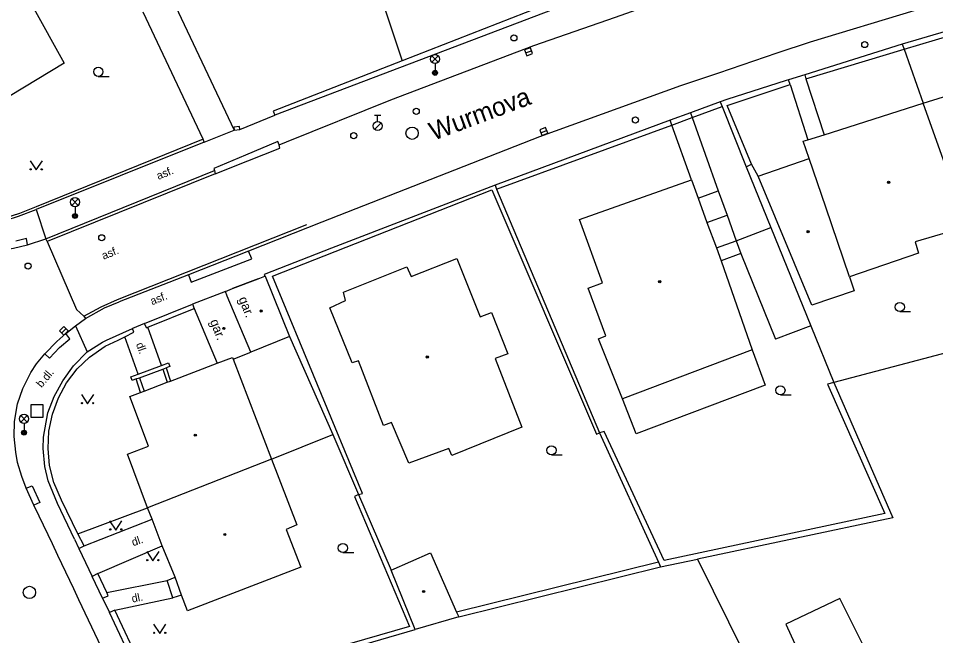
# Model space of a CAD drawing. Extents: x -600391 to -599491, y -1160176 to -1159402.
# Drawn here: x -600225 to -600150.5, y -1159694.5 to -1159644.4 of the extents above; entities that cross this region are included whole.
import ezdxf

# ---------------------------------------------------------------- set-up
doc = ezdxf.new("R2010")
doc.units = 0
for name, color, linetype in [('Level 10', 7, 'Continuous'), ('Level 11', 7, 'Continuous'), ('Level 26', 7, 'Continuous'), ('Level 27', 7, 'Continuous'), ('Level 28', 7, 'Continuous'), ('Level 33', 7, 'Continuous'), ('Level 36', 7, 'Continuous'), ('Level 39', 7, 'Continuous'), ('Level 40', 7, 'Continuous'), ('Level 41', 7, 'Continuous'), ('Level 5', 7, 'Continuous'), ('Level 50', 7, 'Continuous'), ('Level 51', 7, 'Continuous'), ('Level 6', 7, 'Continuous'), ('Level 7', 7, 'Continuous'), ('Level 8', 7, 'Continuous')]:
    doc.layers.add(name, color=color, linetype=linetype)

msp = doc.modelspace()

# ---------------------------------------------------------------- linework, layer by layer
at = {"layer": 'Level 10'}
for points in [[(-600203.81, -1159654.71), (-600203.2, -1159654.46), (-600194.73, -1159651.05), (-600183.13, -1159646.66), (-600176.51, -1159644.35), (-600173.89, -1159643.43), (-600161.79, -1159639.45), (-600139.81, -1159632.73), (-600117.42, -1159627.38), (-600101.85, -1159624.11), (-600096.85, -1159623.48), (-600094.37, -1159623.17), (-600090.07, -1159622.63), (-600079.63, -1159622.19), (-600061.86, -1159622.84)], [(-600091.45, -1159629.86), (-600119.7, -1159635.07), (-600134.36, -1159638.83), (-600136.31, -1159639.33), (-600143.85, -1159641.26), (-600160.7, -1159646.37), (-600163.4, -1159647.28), (-600168.14, -1159648.88), (-600171.23, -1159649.93), (-600182.66, -1159654.06), (-600190.19, -1159657.01), (-600200.329, -1159660.99), (-600206.29, -1159663.33)], [(-600208.99, -1159657.06), (-600206.35, -1159656.02), (-600203.75, -1159654.97), (-600203.81, -1159654.71)], [(-600222.75, -1159662.34), (-600209.07, -1159656.8)], [(-600209.07, -1159656.8), (-600208.99, -1159657.06)], [(-600224.23, -1159662.82), (-600222.75, -1159662.34)], [(-600226.58, -1159663.28), (-600225.37, -1159663.1), (-600224.23, -1159662.82)], [(-600206.29, -1159663.33), (-600211.18, -1159665.25)], [(-600211.18, -1159665.25), (-600216.81, -1159667.45)], [(-600219.54, -1159668.81), (-600218, -1159667.95), (-600216.81, -1159667.45)], [(-600220.33, -1159669.41), (-600219.54, -1159668.81)], [(-600221.14, -1159670.03), (-600220.33, -1159669.41)], [(-600222.84, -1159671.66), (-600221.85, -1159670.68), (-600221.14, -1159670.03)], [(-600224.35, -1159682.57), (-600224.7, -1159681.62), (-600225.05, -1159680.48), (-600225.18, -1159679.65), (-600225.32, -1159678.37), (-600225.29, -1159677.17), (-600225.05, -1159675.73), (-600224.62, -1159674.49), (-600223.97, -1159673.19), (-600223.52, -1159672.49), (-600222.84, -1159671.66)], [(-600223.72, -1159683.94), (-600224.35, -1159682.57)], [(-600197.66, -1159738.93), (-600199.99, -1159733.97), (-600200.43, -1159733.05), (-600201.7, -1159730.35), (-600202.12, -1159729.41), (-600205.92, -1159721.47), (-600206.37, -1159720.55), (-600209.98, -1159712.86), (-600210.42, -1159711.95), (-600217.28, -1159697.51), (-600217.72, -1159696.59), (-600220.08, -1159691.63), (-600220.49, -1159690.73), (-600221.79, -1159688.03), (-600222.22, -1159687.1), (-600223.28, -1159684.84), (-600223.72, -1159683.94)]]:
    msp.add_lwpolyline(points, dxfattribs=at)
at = {"layer": 'Level 11'}
for points in [[(-600209.99, -1159654.25), (-600214.85, -1159643.95)], [(-600161.04, -1159649.35), (-600159.57, -1159653.89)], [(-600162.32, -1159649.81), (-600160.88, -1159654.3)], [(-600171.93, -1159653.1), (-600170.28, -1159652.49)], [(-600170.28, -1159652.49), (-600168.15, -1159658.45)], [(-600170.34, -1159657.54), (-600171.93, -1159653.1)], [(-600203.81, -1159654.71), (-600203.92, -1159654.45), (-600206.53, -1159655.55), (-600209.1, -1159656.63), (-600209.07, -1159656.8)], [(-600164.91, -1159657.24), (-600165.45, -1159656.27)], [(-600208.99, -1159657.06), (-600222.63, -1159662.55)], [(-600169.79, -1159659.04), (-600168.15, -1159658.45)], [(-600168.15, -1159658.45), (-600167.44, -1159660.43)], [(-600223.53, -1159659.97), (-600222.75, -1159662.34)], [(-600169.07, -1159661.01), (-600167.44, -1159660.43)], [(-600167.44, -1159660.43), (-600166.7, -1159662.5)], [(-600219.66, -1159668.6), (-600218.25, -1159667.85), (-600216.93, -1159667.27), (-600201.55, -1159661.18)], [(-600166.7, -1159662.5), (-600163.89, -1159661.43)], [(-600224.23, -1159662.82), (-600224.33, -1159662.3), (-600225.2, -1159662.53)], [(-600222.63, -1159662.55), (-600222.65, -1159662.56), (-600222.75, -1159662.34)], [(-600222.63, -1159662.55), (-600220.27, -1159668.06), (-600219.66, -1159668.6)], [(-600168.31, -1159663.08), (-600166.7, -1159662.5)], [(-600166.7, -1159662.5), (-600166.33, -1159663.53)], [(-600211.18, -1159665.25), (-600210.94, -1159665.86), (-600206.02, -1159663.97), (-600206.29, -1159663.33)], [(-600166.33, -1159663.53), (-600167.93, -1159664.11)], [(-600166.33, -1159663.53), (-600163.5, -1159670.47)], [(-600219.66, -1159668.6), (-600219.54, -1159668.81)], [(-600220.33, -1159669.41), (-600219.39, -1159671.52)], [(-600213.36, -1159672.62), (-600214.48, -1159669.5)], [(-600160.65, -1159669.39), (-600163.5, -1159670.47)], [(-600222.84, -1159671.66), (-600222.45, -1159672.02), (-600221.64, -1159671.16), (-600220.8, -1159670.44), (-600221.14, -1159670.03)], [(-600215.26, -1159673.32), (-600216.34, -1159670.29)], [(-600165.41, -1159671.35), (-600164.35, -1159674.2), (-600174.81, -1159678.17), (-600175.94, -1159675.32)], [(-600215.43, -1159673.71), (-600215.74, -1159673.83), (-600215.85, -1159673.54), (-600215.26, -1159673.32), (-600213.36, -1159672.62), (-600212.78, -1159672.4), (-600212.68, -1159672.69), (-600212.98, -1159672.8)], [(-600215.15, -1159673.61), (-600213.26, -1159672.91)], [(-600213.26, -1159672.91), (-600212.98, -1159672.8)], [(-600213.26, -1159672.91), (-600212.89, -1159673.98)], [(-600212.98, -1159672.8), (-600212.62, -1159673.88)], [(-600215.43, -1159673.71), (-600215.15, -1159673.61)], [(-600215.07, -1159674.81), (-600215.43, -1159673.71)], [(-600215.15, -1159673.61), (-600214.76, -1159674.69)], [(-600224.35, -1159682.57), (-600223.86, -1159682.38), (-600223.23, -1159683.73), (-600223.72, -1159683.94)], [(-600220.14, -1159686.27), (-600214.49, -1159684.17)], [(-600219.65, -1159687.26), (-600214.13, -1159685.09)], [(-600218.53, -1159689.51), (-600213.3, -1159687.24)], [(-600217.81, -1159691.03), (-600212.91, -1159690.07)], [(-600217.14, -1159692.47), (-600212.43, -1159691.46)], [(-600162.66, -1159693.62), (-600160.75, -1159697.8), (-600156.28, -1159695.54), (-600158.28, -1159691.52), (-600162.66, -1159693.62)]]:
    msp.add_lwpolyline(points, dxfattribs=at)
at = {"layer": 'Level 26'}
msp.add_lwpolyline([(-600223.97, -1159676.82), (-600222.97, -1159676.82), (-600222.97, -1159675.82), (-600223.97, -1159675.82)], close=True, dxfattribs=at)
at = {"layer": 'Level 27'}
for p, q in [((-600183.795, -1159647.246), (-600183.325, -1159647.074)), ((-600182.563, -1159653.722), (-600182.097, -1159653.538)), ((-600221.457, -1159669.977), (-600221.103, -1159669.623))]:
    msp.add_line(p, q, dxfattribs=at)
for points in [[(-600183.708, -1159647.481), (-600183.239, -1159647.308), (-600183.412, -1159646.839), (-600183.881, -1159647.011)], [(-600182.471, -1159653.954), (-600182.006, -1159653.771), (-600182.189, -1159653.306), (-600182.654, -1159653.489)], [(-600221.28, -1159670.154), (-600220.926, -1159669.8), (-600221.28, -1159669.446), (-600221.634, -1159669.8)]]:
    msp.add_lwpolyline(points, close=True, dxfattribs=at)
for centre in [(-600193.01, -1159653.77), (-600224.08, -1159691.03)]:
    msp.add_circle(centre, 0.5, dxfattribs=at)
at = {"layer": 'Level 28'}
for p, q in [((-600196.06, -1159652.305), (-600195.56, -1159652.305)), ((-600195.81, -1159652.805), (-600195.81, -1159652.305)), ((-600196.068, -1159653.452), (-600195.538, -1159652.922))]:
    msp.add_line(p, q, dxfattribs=at)
for centre, radius in [((-600184.75, -1159646.03), 0.25), ((-600156.26, -1159646.57), 0.25), ((-600192.68, -1159651.99), 0.25), ((-600174.88, -1159652.69), 0.25), ((-600195.81, -1159653.18), 0.375), ((-600197.75, -1159653.96), 0.25), ((-600218.21, -1159662.25), 0.25), ((-600224.19, -1159664.55), 0.25)]:
    msp.add_circle(centre, radius, dxfattribs=at)
at = {"layer": 'Level 33'}
for p, q in [((-600191.415, -1159648.01), (-600190.885, -1159647.48)), ((-600191.415, -1159647.48), (-600190.885, -1159648.01)), ((-600191.15, -1159648.12), (-600191.15, -1159648.87)), ((-600220.645, -1159659.62), (-600220.115, -1159659.09)), ((-600220.645, -1159659.09), (-600220.115, -1159659.62)), ((-600220.38, -1159659.73), (-600220.38, -1159660.48)), ((-600224.785, -1159677.21), (-600224.255, -1159676.68)), ((-600224.785, -1159676.68), (-600224.255, -1159677.21)), ((-600224.52, -1159677.32), (-600224.52, -1159678.07))]:
    msp.add_line(p, q, dxfattribs=at)
for centre, radius in [((-600191.15, -1159647.745), 0.375), ((-600191.15, -1159648.87), 0.2), ((-600191.15, -1159648.87), 0.145), ((-600191.15, -1159648.87), 0.0876), ((-600220.38, -1159659.355), 0.375), ((-600220.38, -1159660.48), 0.2), ((-600220.38, -1159660.48), 0.145), ((-600220.38, -1159660.48), 0.0876), ((-600224.52, -1159676.945), 0.375), ((-600224.52, -1159678.07), 0.2), ((-600224.52, -1159678.07), 0.145), ((-600224.52, -1159678.07), 0.0876)]:
    msp.add_circle(centre, radius, dxfattribs=at)
at = {"layer": 'Level 36'}
for p, q in [((-600218.49, -1159649.155), (-600217.615, -1159649.155)), ((-600153.42, -1159668.245), (-600152.545, -1159668.245)), ((-600163.11, -1159675.005), (-600162.235, -1159675.005)), ((-600181.7, -1159679.875), (-600180.825, -1159679.875)), ((-600198.63, -1159687.805), (-600197.755, -1159687.805))]:
    msp.add_line(p, q, dxfattribs=at)
for points in [[(-600224.03, -1159656), (-600223.53, -1159656.75), (-600223.03, -1159656)], [(-600219.86, -1159674.97), (-600219.36, -1159675.72), (-600218.86, -1159674.97)], [(-600217.57, -1159685.22), (-600217.07, -1159685.97), (-600216.57, -1159685.22)], [(-600214.56, -1159687.71), (-600214.06, -1159688.46), (-600213.56, -1159687.71)], [(-600214, -1159693.61), (-600213.5, -1159694.36), (-600213, -1159693.61)]]:
    msp.add_lwpolyline(points, dxfattribs=at)
for centre, radius in [((-600218.49, -1159648.78), 0.375), ((-600223.98, -1159656.7), 0.05), ((-600223.081, -1159656.7), 0.05), ((-600153.42, -1159667.87), 0.375), ((-600163.11, -1159674.63), 0.375), ((-600219.81, -1159675.67), 0.05), ((-600218.911, -1159675.67), 0.05), ((-600181.7, -1159679.5), 0.375), ((-600217.52, -1159685.92), 0.05), ((-600216.621, -1159685.92), 0.05), ((-600198.63, -1159687.43), 0.375), ((-600214.51, -1159688.41), 0.05), ((-600213.611, -1159688.41), 0.05), ((-600213.95, -1159694.31), 0.05), ((-600213.051, -1159694.31), 0.05)]:
    msp.add_circle(centre, radius, dxfattribs=at)
at = {"layer": 'Level 39'}
for centre, radius in [((-600154.32, -1159657.75), 0.09), ((-600154.32, -1159657.75), 0.0398), ((-600160.86, -1159661.76), 0.09), ((-600160.86, -1159661.76), 0.0398), ((-600172.91, -1159665.82), 0.09), ((-600172.91, -1159665.82), 0.0398), ((-600205.27, -1159668.19), 0.09), ((-600205.27, -1159668.19), 0.0398), ((-600208.3, -1159669.61), 0.09), ((-600208.3, -1159669.61), 0.0398), ((-600191.78, -1159671.93), 0.09), ((-600191.78, -1159671.93), 0.0398), ((-600210.62, -1159678.27), 0.09), ((-600210.62, -1159678.27), 0.0398), ((-600208.22, -1159686.33), 0.09), ((-600208.22, -1159686.33), 0.0398), ((-600192.08, -1159690.96), 0.09), ((-600192.08, -1159690.96), 0.0398)]:
    msp.add_circle(centre, radius, dxfattribs=at)
at = {"layer": 'Level 5'}
for points in [[(-600223.86, -1159643.39), (-600221.27, -1159648.07)], [(-600221.27, -1159648.07), (-600225.65, -1159650.73)], [(-600151.51, -1159651.33), (-600146.13, -1159649.64)], [(-600159.57, -1159653.89), (-600151.51, -1159651.33)], [(-600149.59, -1159656.7), (-600151.51, -1159651.33)], [(-600160.88, -1159654.3), (-600159.57, -1159653.89)], [(-600161.25, -1159654.42), (-600160.88, -1159654.3)], [(-600160.77, -1159655.83), (-600161.25, -1159654.42)], [(-600164.91, -1159657.24), (-600160.77, -1159655.83)], [(-600159.43, -1159659.77), (-600160.77, -1159655.83)], [(-600179.41, -1159660.78), (-600170.34, -1159657.54)], [(-600170.34, -1159657.54), (-600169.79, -1159659.04)], [(-600160.56, -1159667.71), (-600164.91, -1159657.24)], [(-600169.79, -1159659.04), (-600169.07, -1159661.01)], [(-600157.51, -1159665.42), (-600159.43, -1159659.77)], [(-600177.55, -1159665.91), (-600179.41, -1159660.78)], [(-600169.07, -1159661.01), (-600168.31, -1159663.08)], [(-600147.93, -1159661.35), (-600152.17, -1159662.59)], [(-600168.31, -1159663.08), (-600167.93, -1159664.11)], [(-600152.17, -1159662.59), (-600151.9, -1159663.51)], [(-600151.9, -1159663.51), (-600157.51, -1159665.42)], [(-600193.09, -1159665.39), (-600189.39, -1159663.94)], [(-600189.39, -1159663.94), (-600187.5, -1159668.67)], [(-600167.93, -1159664.11), (-600165.41, -1159671.35)], [(-600198.58, -1159666.67), (-600193.43, -1159664.6)], [(-600193.43, -1159664.6), (-600193.09, -1159665.39)], [(-600207.6, -1159666.38), (-600205.52, -1159665.58)], [(-600205.52, -1159665.58), (-600204.96, -1159665.37)], [(-600204.96, -1159665.37), (-600204.93, -1159665.36)], [(-600204.93, -1159665.36), (-600202.97, -1159670.27)], [(-600178.73, -1159666.35), (-600177.55, -1159665.91)], [(-600157.51, -1159665.42), (-600157.13, -1159666.55)], [(-600208.17, -1159666.61), (-600210.85, -1159667.63)], [(-600208.17, -1159666.61), (-600207.6, -1159666.38)], [(-600208.02, -1159667), (-600208.17, -1159666.61)], [(-600198.41, -1159667.34), (-600198.58, -1159666.67)], [(-600177.28, -1159670.22), (-600178.73, -1159666.35)], [(-600157.13, -1159666.55), (-600160.56, -1159667.71)], [(-600206.12, -1159671.53), (-600208.02, -1159667)], [(-600199.7, -1159667.95), (-600198.41, -1159667.34)], [(-600210.85, -1159667.63), (-600210.7, -1159667.98)], [(-600210.7, -1159667.98), (-600208.83, -1159672.44)], [(-600197.89, -1159672.39), (-600199.7, -1159667.95)], [(-600187.5, -1159668.67), (-600186.58, -1159668.32)], [(-600186.58, -1159668.32), (-600185.24, -1159671.66)], [(-600202.97, -1159670.27), (-600206.12, -1159671.53)], [(-600177.87, -1159670.44), (-600177.28, -1159670.22)], [(-600175.94, -1159675.32), (-600177.87, -1159670.44)], [(-600208.83, -1159672.44), (-600207.59, -1159671.97)], [(-600207.59, -1159671.97), (-600207.54, -1159672.1)], [(-600207.54, -1159672.1), (-600206.12, -1159671.53)], [(-600185.24, -1159671.66), (-600186.27, -1159672.05)], [(-600165.41, -1159671.35), (-600175.94, -1159675.32)], [(-600212.62, -1159673.88), (-600208.83, -1159672.44)], [(-600207.54, -1159672.1), (-600204.43, -1159680.21)], [(-600197.36, -1159672.23), (-600197.89, -1159672.39)], [(-600195.33, -1159677.48), (-600197.36, -1159672.23)], [(-600186.27, -1159672.05), (-600184.1, -1159677.62)], [(-600214.76, -1159674.69), (-600212.89, -1159673.98)], [(-600212.89, -1159673.98), (-600212.62, -1159673.88)], [(-600215.93, -1159675.14), (-600215.07, -1159674.81)], [(-600215.07, -1159674.81), (-600214.76, -1159674.69)], [(-600214.41, -1159679.15), (-600215.93, -1159675.14)], [(-600194.68, -1159677.25), (-600195.33, -1159677.48)], [(-600193.29, -1159680.54), (-600194.68, -1159677.25)], [(-600184.1, -1159677.62), (-600189.78, -1159679.92)], [(-600216.12, -1159679.82), (-600214.41, -1159679.15)], [(-600190.02, -1159679.35), (-600193.29, -1159680.54)], [(-600189.78, -1159679.92), (-600190.02, -1159679.35)], [(-600214.49, -1159684.17), (-600216.12, -1159679.82)], [(-600204.43, -1159680.21), (-600214.49, -1159684.17)], [(-600204.43, -1159680.21), (-600202.38, -1159685.54)], [(-600214.13, -1159685.09), (-600214.49, -1159684.17)], [(-600213.3, -1159687.24), (-600214.13, -1159685.09)], [(-600202.38, -1159685.54), (-600203.23, -1159685.92)], [(-600203.23, -1159685.92), (-600202.06, -1159688.99)], [(-600212.25, -1159689.79), (-600213.3, -1159687.24)], [(-600194.7, -1159689.23), (-600191.51, -1159687.82)], [(-600191.51, -1159687.82), (-600189.4, -1159692.63)], [(-600202.06, -1159688.99), (-600211.25, -1159692.52)], [(-600212.91, -1159690.07), (-600212.25, -1159689.79)], [(-600211.74, -1159691.26), (-600212.25, -1159689.79)], [(-600192.77, -1159694.04), (-600194.7, -1159689.23)], [(-600212.43, -1159691.46), (-600212.91, -1159690.07)], [(-600211.74, -1159691.26), (-600212.43, -1159691.46)], [(-600211.25, -1159692.52), (-600211.74, -1159691.26)], [(-600189.4, -1159692.63), (-600189.22, -1159693.02)], [(-600189.22, -1159693.02), (-600192.77, -1159694.04)]]:
    msp.add_lwpolyline(points, dxfattribs=at)
at = {"layer": 'Level 51'}
msp.add_lwpolyline([(-600199.57, -1159630.68), (-600193.81, -1159647.88)], dxfattribs=at)
at = {"layer": 'Level 6'}
msp.add_lwpolyline([(-600205.52, -1159665.58), (-600207.6, -1159666.38)], dxfattribs=at)
at = {"layer": 'Level 7'}
for points in [[(-600174.96, -1159640.52), (-600193.81, -1159647.88), (-600204.28, -1159651.97), (-600204.16, -1159652.29)], [(-600174.75, -1159641.11), (-600177.29, -1159642.08), (-600204.16, -1159652.29)], [(-600212.48, -1159642.92), (-600207.47, -1159653.53)], [(-600147.6, -1159644.9), (-600153.23, -1159646.53)], [(-600153.07, -1159646.95), (-600147.97, -1159645.42), (-600147.27, -1159647.63), (-600146.79, -1159647.49)], [(-600153.23, -1159646.53), (-600161.14, -1159649.03)], [(-600153.23, -1159646.53), (-600153.07, -1159646.95)], [(-600161.04, -1159649.35), (-600153.07, -1159646.95)], [(-600153.07, -1159646.95), (-600151.51, -1159651.33)], [(-600162.45, -1159649.44), (-600162.65, -1159649.5), (-600167.45, -1159651.03), (-600168.01, -1159651.21)], [(-600162.32, -1159649.81), (-600162.45, -1159649.44)], [(-600161.14, -1159649.03), (-600161.04, -1159649.35)], [(-600165.9, -1159656.5), (-600165.45, -1159656.27), (-600167.44, -1159651.53), (-600162.32, -1159649.81)], [(-600168.01, -1159651.21), (-600170.42, -1159652.1)], [(-600170.28, -1159652.49), (-600167.85, -1159651.6)], [(-600168.01, -1159651.21), (-600167.85, -1159651.6)], [(-600167.85, -1159651.6), (-600165.9, -1159656.5)], [(-600170.42, -1159652.1), (-600170.28, -1159652.49)], [(-600206.99, -1159653.47), (-600207.02, -1159653.21), (-600207.5, -1159653.27), (-600207.47, -1159653.53)], [(-600172.07, -1159652.71), (-600186.28, -1159657.98)], [(-600186.15, -1159658.3), (-600171.93, -1159653.1)], [(-600171.93, -1159653.1), (-600172.07, -1159652.71)], [(-600207.47, -1159653.53), (-600206.99, -1159653.47)], [(-600209.89, -1159654.49), (-600209.99, -1159654.25), (-600223.54, -1159659.75)], [(-600209.89, -1159654.49), (-600223.53, -1159659.97)], [(-600223.54, -1159659.75), (-600224.89, -1159660.27), (-600226, -1159660.62), (-600226.83, -1159660.67), (-600227.84, -1159660.68), (-600228.6, -1159660.59), (-600229.42, -1159660.41), (-600230.8, -1159659.86), (-600231.35, -1159659.51), (-600232.36, -1159658.62), (-600233.22, -1159657.71), (-600233.75, -1159657.08)], [(-600165.9, -1159656.5), (-600163.89, -1159661.43), (-600160.65, -1159669.39), (-600158.77, -1159673.99)], [(-600186.28, -1159657.98), (-600199.556, -1159663.106), (-600205.03, -1159665.22)], [(-600197.36, -1159683.08), (-600197.03, -1159683.01), (-600204.34, -1159665.37), (-600186.53, -1159658.35), (-600178.05, -1159678.18), (-600177.79, -1159678.09)], [(-600186.28, -1159657.98), (-600186.15, -1159658.3)], [(-600186.15, -1159658.3), (-600177.79, -1159678.09)], [(-600225.97, -1159660.81), (-600224.96, -1159660.51), (-600223.53, -1159659.97)], [(-600205.03, -1159665.22), (-600204.96, -1159665.37)], [(-600214.73, -1159669.22), (-600210.85, -1159667.63)], [(-600214.59, -1159669.55), (-600214.48, -1159669.5), (-600210.7, -1159667.98)], [(-600219.39, -1159671.52), (-600218.15, -1159670.72), (-600217.82, -1159670.57), (-600215.71, -1159669.61)], [(-600215.6, -1159669.92), (-600215.71, -1159669.61)], [(-600214.59, -1159669.55), (-600214.73, -1159669.22)], [(-600222.1, -1159682.1), (-600222.44, -1159680.73), (-600222.57, -1159679.34), (-600222.5, -1159677.94), (-600222.21, -1159676.57), (-600221.73, -1159675.25), (-600221.06, -1159674.02), (-600220.21, -1159672.9), (-600219.2, -1159671.93), (-600217.93, -1159671.06), (-600216.88, -1159670.57), (-600216.34, -1159670.29), (-600215.6, -1159669.92)], [(-600202.97, -1159670.27), (-600199.46, -1159678.22)], [(-600144.73, -1159670.29), (-600158.77, -1159673.99)], [(-600222.55, -1159681.99), (-600222.83, -1159680.8), (-600222.97, -1159679.35), (-600222.94, -1159678.42), (-600222.6, -1159676.46), (-600222.08, -1159675.14), (-600221.38, -1159673.86), (-600220.51, -1159672.64), (-600219.39, -1159671.52)], [(-600158.77, -1159673.99), (-600159.29, -1159674.14), (-600154.63, -1159684.63), (-600172.56, -1159688.44), (-600177.41, -1159677.96), (-600177.79, -1159678.09)], [(-600158.77, -1159673.99), (-600153.99, -1159684.97)], [(-600204.43, -1159680.21), (-600199.46, -1159678.22)], [(-600199.46, -1159678.22), (-600197.36, -1159683.08)], [(-600177.79, -1159678.09), (-600173.02, -1159688.57)], [(-600220.43, -1159686.71), (-600221.8, -1159683.81), (-600222.55, -1159681.99)], [(-600220.06, -1159687.47), (-600219.65, -1159687.26), (-600220.14, -1159686.27), (-600221.49, -1159683.54), (-600222.1, -1159682.1)], [(-600197.36, -1159683.08), (-600197.68, -1159683.24), (-600193.22, -1159693.79), (-600213.74, -1159699.72), (-600213.97, -1159699.23), (-600214.39, -1159699.41)], [(-600197.36, -1159683.08), (-600194.7, -1159689.23)], [(-600153.99, -1159684.97), (-600169.84, -1159688.34)], [(-600220.43, -1159686.71), (-600220.06, -1159687.47)], [(-600172.84, -1159688.96), (-600169.84, -1159688.34)], [(-600169.84, -1159688.34), (-600166.06, -1159695.99)], [(-600173.02, -1159688.57), (-600189.4, -1159692.63)], [(-600189.22, -1159693.02), (-600172.84, -1159688.96)], [(-600173.02, -1159688.57), (-600172.84, -1159688.96)], [(-600218.14, -1159691.51), (-600217.68, -1159691.31), (-600217.81, -1159691.03), (-600218.53, -1159689.51), (-600218.98, -1159689.74)], [(-600218.14, -1159691.51), (-600218.98, -1159689.74)], [(-600215.5, -1159697.11), (-600215.06, -1159696.9), (-600217.14, -1159692.47), (-600217.58, -1159692.67)], [(-600215.5, -1159697.11), (-600217.58, -1159692.67)], [(-600214, -1159700.22), (-600213.58, -1159700.1), (-600192.77, -1159694.04)]]:
    msp.add_lwpolyline(points, dxfattribs=at)
at = {"layer": 'Level 8'}
for points in [[(-600161.14, -1159649.03), (-600162.45, -1159649.44)], [(-600206.99, -1159653.47), (-600204.16, -1159652.29)], [(-600170.42, -1159652.1), (-600172.07, -1159652.71)], [(-600209.89, -1159654.49), (-600207.47, -1159653.53)], [(-600214.73, -1159669.22), (-600215.71, -1159669.61)], [(-600220.06, -1159687.47), (-600218.98, -1159689.74)], [(-600218.14, -1159691.51), (-600217.58, -1159692.67)]]:
    msp.add_lwpolyline(points, dxfattribs=at)

# ---------------------------------------------------------------- texts
at = {"layer": 'Level 40'}
for s, rotation, p in [('asf.', 22.05, (-600213.61, -1159657.56)), ('asf.', 21.92, (-600218.06, -1159664.04)), ('asf.', 22.05, (-600214.12, -1159667.73)), ('dl.', 289.65382, (-600215.44, -1159670.88)), ('b.dl. ', 50.14, (-600223.1, -1159674.46)), ('dl.', 18.72279, (-600215.66, -1159687.29)), ('dl.', 11.11932, (-600215.72, -1159691.86))]:
    msp.add_text(s, height=0.65, rotation=rotation, dxfattribs=at).set_placement(p)
at = {"layer": 'Level 41'}
for p in [(-600207.11, -1159667.2), (-600209.44, -1159669.03)]:
    msp.add_text('gar.', height=0.75, rotation=291.45, dxfattribs=at).set_placement(p)
at = {"layer": 'Level 50'}
msp.add_text('Wurmova', height=1.5, rotation=20.48686, dxfattribs=at).set_placement((-600191.28, -1159654.386))
msp.add_text('Wurmova', height=1.5, rotation=20.48686, dxfattribs=at).set_placement((-600191.28, -1159654.386))
msp.add_text('Wurmova', height=1.5, rotation=20.48686, dxfattribs=at).set_placement((-600191.28, -1159654.386))

doc.saveas('drawing.dxf')
